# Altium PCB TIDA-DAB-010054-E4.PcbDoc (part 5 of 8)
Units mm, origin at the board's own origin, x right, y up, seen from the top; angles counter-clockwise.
Board outline 300 x 180 mm, 4 copper layers (Top Layer, Inner Layer1, Inner Layer2, Bottom Layer), stack 1.605 mm thick; 873 components, 388 nets, 2405 pads, 1542 vias.
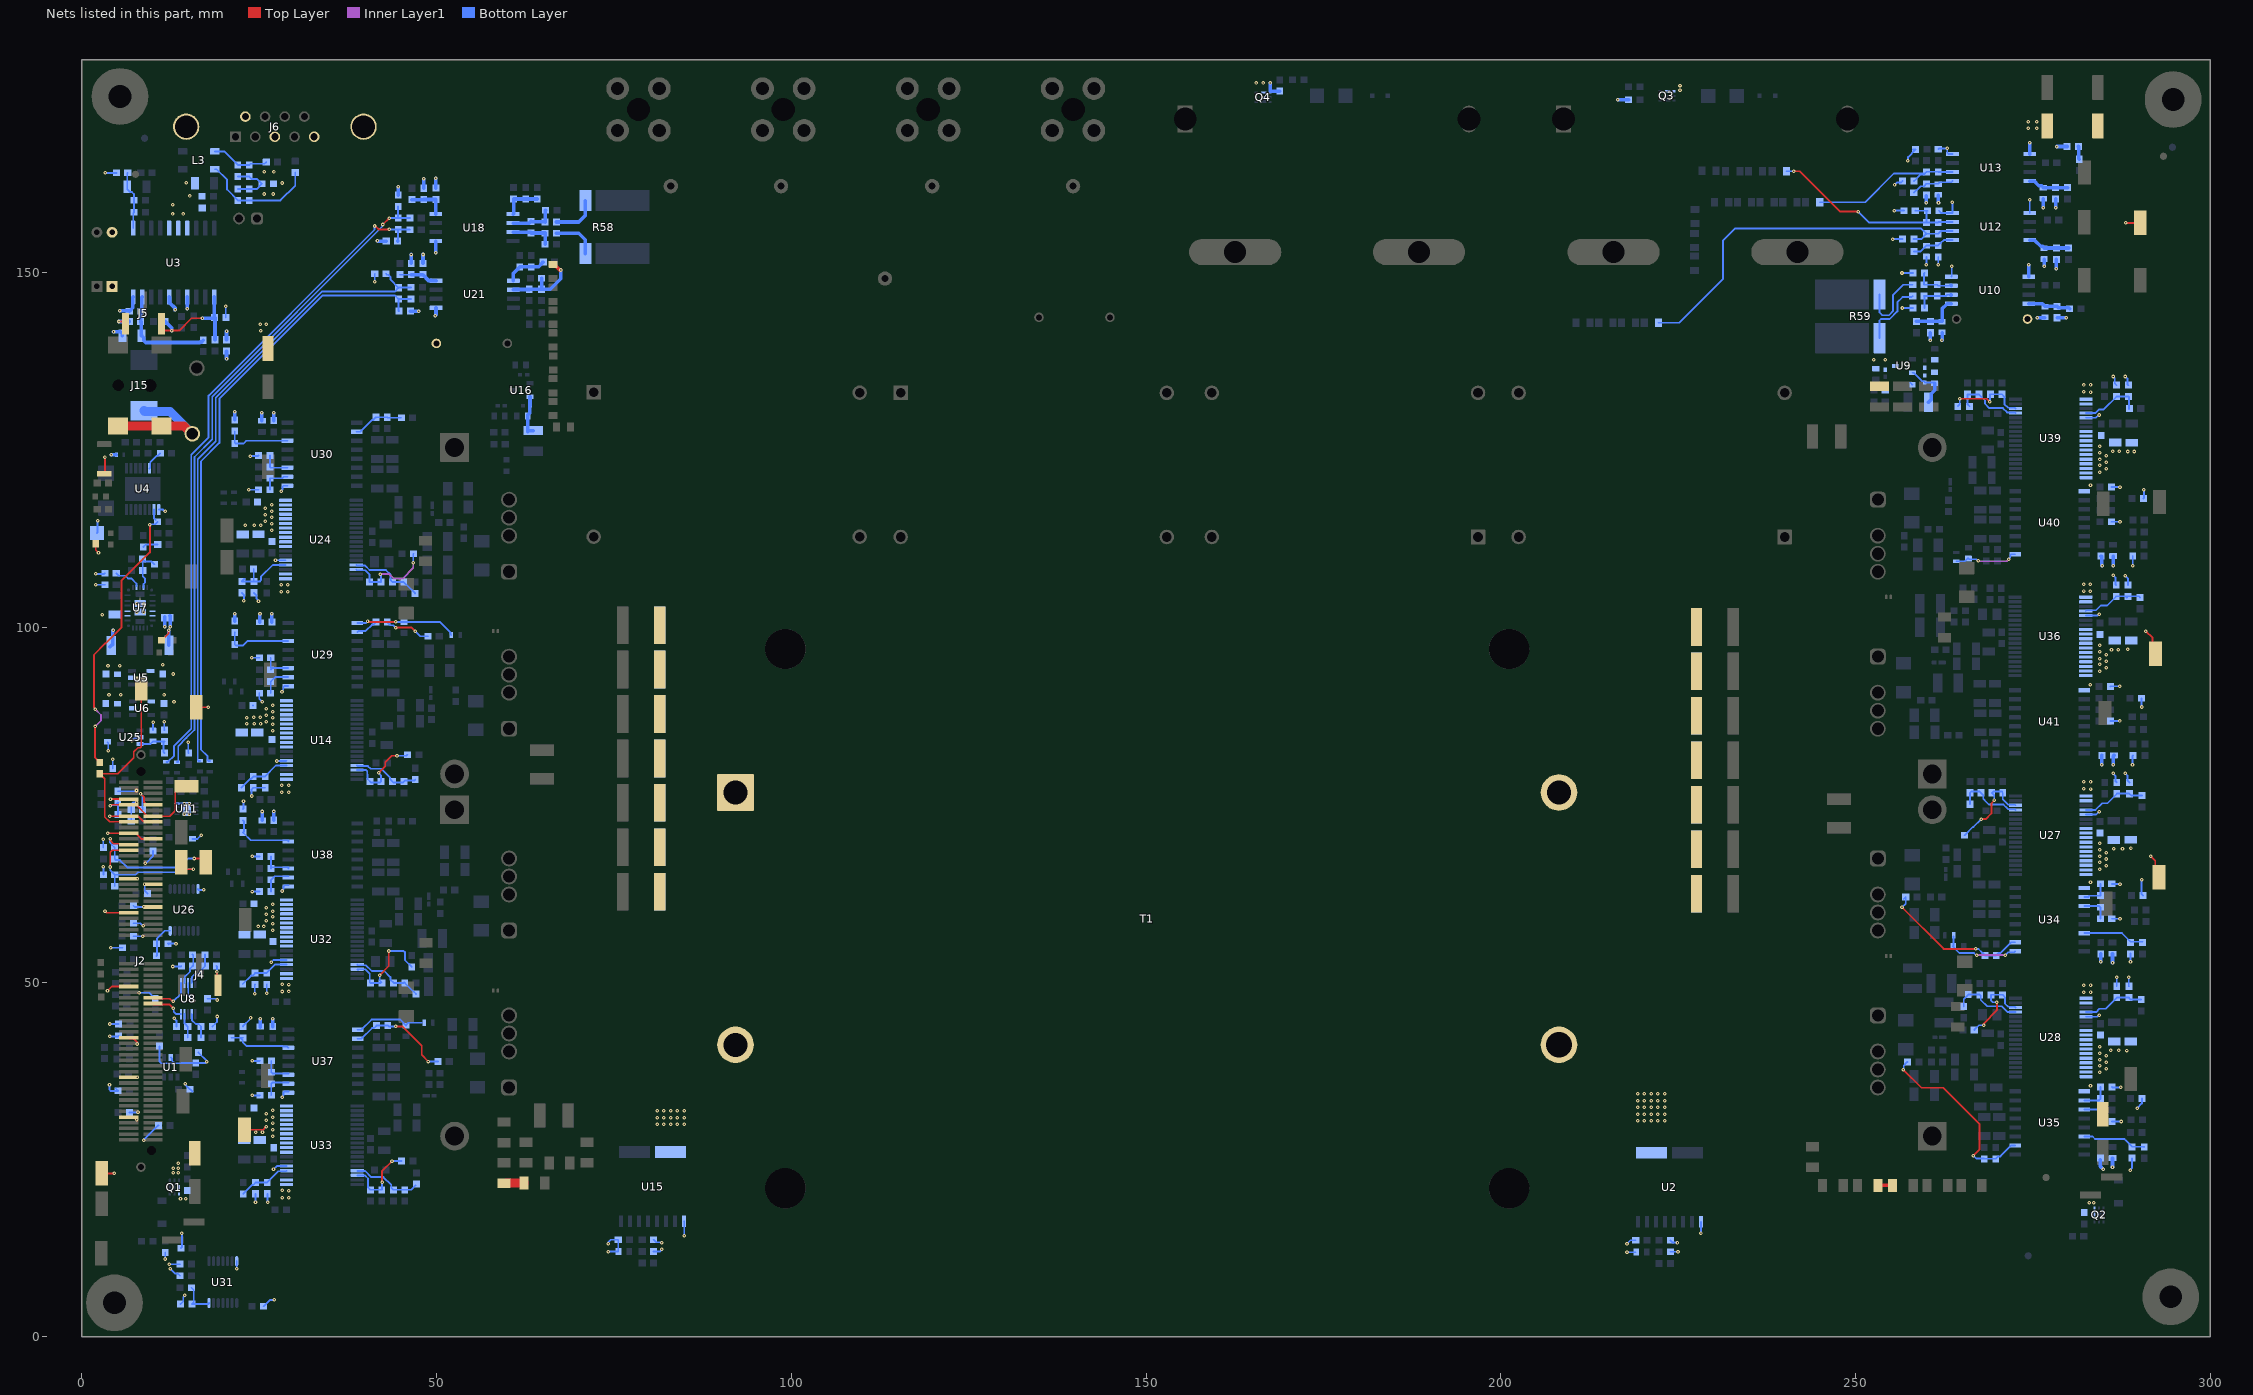
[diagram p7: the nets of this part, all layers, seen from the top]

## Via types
v1: diameter 0.5, hole 0.2, Top Layer to Bottom Layer, tented both sides, 1530 vias
v2: diameter 0.5, hole 0.2, Top Layer to Bottom Layer, 12 vias

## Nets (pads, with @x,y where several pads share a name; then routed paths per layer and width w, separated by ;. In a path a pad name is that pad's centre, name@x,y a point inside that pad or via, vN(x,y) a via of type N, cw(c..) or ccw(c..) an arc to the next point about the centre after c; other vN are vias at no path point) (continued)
GND: C1.2 C60.1 C61.2 C62.2 C63.2 C64.1 C65.2 C67.2 C68.1 C69.2 C70.1 C71.2 C72.2 C73.2 C74.2 C75.2 C77.2 C81.2 C82.2 C93.2 C96.2 C97.2 C98.2 C99.2 C100.2 C107.2 C108.2 C109.2 C110.2 C111.1 C112.2 C113.2 C114.2 C121.2 C122.2 C126.1 C128.2 C131.2 C132.2 C133.2 C134.2 C135.2 C136.2 C137.2 C138.2 C140.1 C141.2 C142.2 C145.2 C146.2 C147.2 C148.1 C149.2 C150.2 C151.2 C152.2 C153.2 C154.2 C155.2 C156.2 C157.2 C158.2 C159.2 C160.2 C175.2 C180.2 C183.2 C184.2 C185.2 C186.1 C187.1 C190.2 C191.1 C192.1 C194.2 C195.2 C197.2 C198.2 C199.2 C200.2 C201.2 C202.2 C203.2 C217.2 C222.2 C225.2 C226.2 C227.2 C228.1 C229.1 C231.2 C232.2 C233.1 C234.1 C236.2 C237.2 C238.2 C254.2 C259.2 C262.2 C264.2 C265.2 C266.1 C268.1 C270.2 C274.1 C275.2 C276.2 C277.2 C282.2 C293.2 C298.1 C299.2 C303.2 C304.2 C305.2 C306.1 C307.1 C309.2 C310.1 C311.1 C313.2 C314.2 C319.1 C320.1 C321.2 C322.2 C323.1 C324.1 C325.2 C326.2 C327.2 C328.2 C329.2 C330.2 C331.2 C332.2 C333.2 C334.2 D7.1 D9.2 J2.7 J2.10 J2.13 J2.16 J2.19 J2.22 J2.35 J2.38 J2.46 J2.47 J2.65 J2.83 J2.97 J2.111 J4.3 J9.1 J15.2 J15.3 L4.2 NT1.1 Q1.4 Q1.7 Q2.4 Q2.7 Q3.4 Q3.7 Q4.4 Q4.7 R2.1 R5.1 R28.2 R40.2 R43.1 R46.2 R51.1 R76.1 R81.1 R90.1 R93.1 R94.1 R99.1 R104.1 R130.1 R133.1 R134.1 R169.2 R174.1 R175.1 R176.1 R177.1 R178.1 R179.1 R180.1 R181.1 R182.1 R232.1 R233.1 R234.1 R235.1 R236.1 R237.1 R238.1 R239.1 R240.1 S1.2 TP11.1 TP25.1 TP26.1 TP27.1 TP28.1 TP29.1 TP31.1 U1.2 U2.3 U4.9 U5.2 U5.4 U6.2 U6.4 U7.5 U7.6 U7.16 U7.17 U7.28 U7.29 U8.3 U10.5 U11.4 U11.9 U12.5 U13.5 U14.1 U14.2 U14.5 U14.8 U14.9 U14.10 U14.11 U14.12 U14.13 U14.14 U14.15 U14.16 U14.17 U14.18 U15.3 U18.5 U21.5 U24.1 U24.2 U24.5 U24.8 U24.9 U24.10 U24.11 U24.12 U24.13 U24.14 U24.15 U24.16 U24.17 U24.18 U25.2 U26.7 U27.1 U27.2 U27.5 U27.8 U27.9 U27.10 U27.11 U27.12 U27.13 U27.14 U27.15 U27.16 U27.17 U27.18 U28.1 U28.2 U28.5 U28.8 U28.9 U28.10 U28.11 U28.12 U28.13 U28.14 U28.15 U28.16 U28.17 U28.18 U29.9 U30.9 U31.7 U32.1 U32.2 U32.5 U32.8 U32.9 U32.10 U32.11 U32.12 U32.13 U32.14 U32.15 U32.16 U32.17 U32.18 U33.1 U33.2 U33.5 U33.8 U33.9 U33.10 U33.11 U33.12 U33.13 U33.14 U33.15 U33.16 U33.17 U33.18 U34.9 U35.9 U36.1 U36.2 U36.5 U36.8 U36.9 U36.10 U36.11 U36.12 U36.13 U36.14 U36.15 U36.16 U36.17 U36.18 U37.9 U38.9 U39.1 U39.2 U39.5 U39.8 U39.9 U39.10 U39.11 U39.12 U39.13 U39.14 U39.15 U39.16 U39.17 U39.18 U40.9 U41.9 | length 311.9
  Top Layer w0.254: R76.1@2,111.77 2.014,111.756 2.014,110.889 2.389,110.514 v1(2.389,110.512) ; TP31.1@2.858,23.044 v1(4.623,23.044) ; S1.2@3.199,121.615 3.302,121.718 v1(3.302,123.985) ; v1(3.308,59.998) 3.528,59.779 J2.47@6.669,59.779 ; v1(3.656,48.786) 4.249,49.379 J2.65@6.669,49.379 ; v1(3.714,70.982) 3.716,70.981 7.632,70.981 8.434,70.179 J2.22@10.069,70.179 ; v1(3.978,73.379) J2.13@6.669,73.379 7.969,73.379 8.769,72.579 J2.16@10.069,72.579 ; v1(4.078,75.779) J2.7@6.669,75.779 ; J2.111@6.669,30.979 6.792,30.856 7.448,30.856 7.712,30.593 v1(7.808,30.593) ; J2.97@6.669,36.579 v1(7.847,36.579) ; J2.83@6.669,42.179 6.792,42.056 7.308,42.056 7.776,41.588 7.776,41.322 v1(7.823,41.275) ; J2.35@6.669,64.579 v1(7.871,64.579) ; v1(8.312,76.563) 8.786,76.09 8.786,75.415 9.222,74.979 J2.10@10.069,74.979 ; v1(8.786,60.595) 8.802,60.579 J2.46@10.069,60.579 ; v1(8.877,63.779) J2.38@10.069,63.779 ; R81.1@11.258,98.161 11.283,98.161 12.268,99.145 12.268,99.519 v1(12.315,99.566) ; TP29.1@16.155,88.714 v1(17.877,88.714) ; v1(19.084,51.441) 19.084,49.671 J4.3@19.202,49.552 ; TP25.1@22.96,29.2 25.584,29.2 25.984,29.6 v1(26.051,29.6) ; v1(288.058,156.98) TP28.1@290.09,156.98 ; v1(290.882,99.462) 291.846,98.498 291.846,96.668 TP26.1@292.252,96.262 ; v1(291.577,67.735) 292.227,67.085 292.227,65.29 TP27.1@292.751,64.766
  Top Layer w1.27: J15.2@5.155,128.386 J15.3@11.255,128.386 14.407,128.386 15.539,127.254 TP11.1@15.621,127.254 ; C314.2@26.11,139.451 C314.2@26.275,139.286
  Bottom Layer w0.254: v1(1.985,107.511) 3.198,107.511 C70.1@3.292,107.605 ; v1(2.014,106) C77.2@3.292,106 ; D9.2@2.18,113.27 2.261,113.352 v1(2.261,115.02) ; C114.2@3.067,68.973 3.067,70.108 v1(3.075,70.116) ; C153.2@3.08,65.131 v1(3.08,66.232) ; C146.2@3.662,83.793 3.767,83.688 v1(3.767,82.591) ; v1(3.937,35.531) 3.937,34.823 4.089,34.671 C107.2@5.156,34.671 C107.2@4.823,35.004 ; v1(3.946,42.344) 5.146,42.344 C323.1@5.22,42.418 ; v1(3.962,44.094) C324.1@5.22,44.094 ; v1(4.099,54.848) R178.1@5.763,54.848 ; C152.2@4.394,80.079 4.394,81.403 v1(4.405,81.414) ; R28.2@5.106,76.885 7.569,76.885 7.678,76.994 v1(7.745,76.994) ; C108.2@6.766,31.632 v1(7.956,31.632) ; v1(7.1,84.043) 7.456,84.399 8.127,84.399 U25.2@8.225,84.498 ; R180.1@7.304,58.277 8.295,58.277 8.635,57.937 v1(8.702,57.937) ; R179.1@7.316,56.453 v1(8.608,56.453) ; R181.1@7.326,60.762 7.492,60.595 v1(8.786,60.595) ; v1(8.101,48.494) 9.545,48.494 10.01,48.029 10.035,48.029 10.383,47.681 C322.2@10.383,47.656 ; v1(8.312,76.563) 8.608,76.268 C128.2@8.608,74.317 ; v1(8.788,27.736) 8.788,27.761 10.824,29.796 C93.2@10.849,29.796 ; v1(8.877,63.779) 8.913,63.743 8.913,62.843 9.261,62.495 R182.1@9.286,62.495 ; v1(8.968,66.732) 9.015,66.779 9.117,66.779 10.064,67.726 C140.1@10.064,68.479 ; C151.2@10.051,85.493 10.09,85.532 v1(10.09,86.621) ; U4.9@10.882,116.587 11.472,116.587 11.684,116.375 v1(11.78,116.375) ; C320.1@11,40.969 11,40.001 10.998,39.999 10.998,38.785 11.221,38.562 13.121,38.562 ; v1(11.667,86.679) 11.667,85.527 R169.2@11.682,85.513 ; v1(11.787,10.973) R240.1@11.787,11.895 ; C154.2@12.289,55.315 C154.2@12.191,55.414 v1(13.311,55.414) ; v1(12.344,10.24) R239.1@13.875,10.24 ; v1(12.5,9.596) 13.18,8.915 13.564,8.915 R236.1@13.875,8.604 ; U1.2@12.578,39.392 12.751,39.219 12.751,38.932 13.121,38.562 ; v1(12.824,52.195) 14.003,52.195 C137.2@14.06,52.252 ; v1(13.064,44.876) 13.372,44.568 C136.2@13.372,43.747 ; U11.4@13.455,75.159 v1(14.455,75.159) ; C197.2@13.949,4.634 13.974,4.634 14.322,4.982 14.322,5.571 14.526,5.775 v1(14.526,5.841) ; R238.1@14.003,12.482 14.148,12.627 v1(14.148,14.605) ; v1@14.574,35.7 v1(14.593,35.7) 14.64,35.652 14.64,35.511 15.263,34.889 C321.2@15.288,34.889 15.313,34.889 C321.2@15.661,34.541 ; U8.3@15.025,49.881 15.025,48.104 v1(15.79,47.339) ; v1(15.046,83.766) 15.046,82.311 C135.2@15.093,82.264 ; C126.1@15.621,70.17 16.338,70.17 v1(16.869,70.701) ; U26.7@16.393,63.121 16.393,63.075 16.484,62.984 v1(17.243,62.984) ; C319.1@16.457,40.07 16.482,40.07 17.626,38.926 17.626,38.799 v1(17.673,38.751) ; 17.46,38.605 C1.2@16.098,38.605 14.144,38.605 14.1,38.562 13.121,38.562 ; C313.2@17.752,47.656 18.902,47.656 19.085,47.473 v1(19.152,47.473) ; C121.2@18.431,43.747 18.456,43.747 18.804,44.095 18.804,44.12 19.109,44.425 v1(19.109,45.146) ; C122.2@19.027,52.252 19.084,52.195 v1(19.084,51.441) ; v1@21.864,9.596 U31.7@21.864,10.677 ; R93.1@22.6,104.862 22.885,104.576 v1(22.885,103.734) ; C265.2@22.737,43.747 22.737,43.772 23.814,44.849 v1(23.814,44.986) ; C270.2@22.751,74.388 22.82,74.457 v1(22.82,75.492) ; v1(23.566,119.377) C180.2@24.944,119.377 ; v1(23.803,124.117) 24.855,124.117 C184.2@24.944,124.206 ; v1(23.959,76.222) 23.959,77.134 R90.1@24.206,77.381 C159.2@25.883,77.381 ; v1(23.998,95.715) 25.054,95.715 C183.2@25.059,95.71 ; v1(24.038,34.034) 25.12,34.034 C254.2@25.145,34.059 ; v1(24.038,38.889) 25.12,38.889 C262.2@25.145,38.914 ; v1(24.038,62.758) 25.095,62.758 C259.2@25.097,62.756 ; v1(24.073,67.702) 25.095,67.702 C264.2@25.097,67.704 ; R177.1@24.16,88.981 R177.1@24.185,88.981 ; C160.2@24.288,104.862 24.636,104.514 24.636,104.057 24.937,103.757 v1(24.937,103.69) ; v1(24.409,48.336) 24.409,49.632 R104.1@24.46,49.682 ; v1(24.511,18.951) R130.1@24.511,20.168 ; C175.2@25.056,90.716 25.056,89.909 v1(25.48,89.484) ; R237.1@25.648,4.319 25.673,4.319 26.566,5.213 v1(27.134,5.213) ; C232.2@26.086,49.682 26.097,49.671 v1(26.097,48.452) ; C236.2@26.162,20.168 26.218,20.111 v1(26.218,18.951) ; v1(26.751,52.816) 27.05,53.115 U32.5@28.905,53.115 ; v1(27.051,23.627) 27.499,24.075 U33.5@28.905,24.075 ; v1(27.331,109.435) U24.5@28.765,109.435 ; v1(27.534,81.153) 27.548,81.167 28.852,81.167 U14.5@28.866,81.181 ; v1@28.14,90.84 28.14,90.907 28.418,91.184 28.418,91.527 28.591,91.7 U29.9@29.116,91.7 ; v1(28.145,119.153) 28.145,119.249 28.317,119.421 28.317,119.768 28.49,119.941 U30.9@29.015,119.941 ; v1@28.179,33.734 28.179,33.801 28.457,34.078 28.457,34.422 28.63,34.595 U37.9@29.155,34.595 ; v1@28.179,62.774 28.179,62.841 28.457,63.118 28.457,63.462 28.63,63.635 U38.9@29.155,63.635 ; C195.2@41.312,149.81 41.319,149.803 v1(41.319,148.701) ; v1(74.22,12.024) 75.625,12.024 C147.2@75.625,13.702 74.573,13.702 74.22,13.35 74.22,13.139 v1(74.231,13.128) ; R46.2@80.607,12.04 80.62,12.052 81.547,12.052 81.547,12.08 81.737,12.271 v1(81.737,12.337) ; C334.2@80.62,13.691 80.968,13.343 81.587,13.343 81.671,13.259 v1(81.737,13.259) ; U15.3@84.912,16.309 84.929,16.292 84.929,14.256 v1(84.945,14.24) ; v1(217.782,11.94) C111.1@219.02,11.94 ; v1(217.782,13.127) 218.275,13.62 C110.2@219.02,13.62 ; C333.2@223.888,13.614 224.218,13.284 v1(224.892,13.284) ; R40.2@223.914,11.989 v1(224.968,11.989) ; v1(228.205,14.6) U2.3@228.205,16.205 ; U12.5@274.543,158.367 v1(274.543,160.223) ; U36.5@282.426,101.638 284.041,101.638 284.256,101.853 v1(284.323,101.853) ; U28.5@282.475,45.12 284.038,45.12 284.246,45.329 v1(284.343,45.329) ; U27.5@282.475,73.605 283.875,73.605 284.246,73.976 v1(284.343,73.976) ; U39.5@282.475,129.53 283.864,129.53 284.246,129.913 v1(284.343,129.913) ; C304.2@285.889,86.793 v1(287.232,86.793) ; C299.2@285.889,91.65 285.923,91.685 v1(287.232,91.685) ; C303.2@286.036,114.861 286.044,114.854 v1(287.252,114.854) ; C293.2@286.036,119.763 286.054,119.745 v1(287.252,119.745) ; C225.2@286.085,58.917 v1(287.252,58.917) ; C217.2@286.085,63.85 286.126,63.808 v1@287.342,63.808 ; C226.2@286.125,30.354 v1(287.432,30.354) ; C222.2@286.125,35.211 286.176,35.161 v1(287.342,35.161) ; v1(286.275,107.344) 286.607,107.011 286.607,106.056 C282.2@286.706,105.957 ; v1(286.3,79.402) 286.3,79.342 286.639,79.003 286.639,78.283 C202.2@286.79,78.132 ; v1(286.3,135.338) 286.3,135.278 286.512,135.066 286.512,134.357 C277.2@286.759,134.109 ; v1(286.8,50.688) 286.8,49.42 C203.2@286.805,49.416 ; v1(287.985,107.278) 288.363,106.9 R133.1@288.363,105.957 ; v1(288.005,79.402) 288.293,79.114 288.293,78.422 R94.1@288.583,78.132 ; v1(288.005,135.338) 288.29,135.053 288.29,134.264 R134.1@288.444,134.109 ; v1(288.48,50.688) 288.48,49.445 R99.1@288.51,49.416 ; v1(288.7,23.487) 288.7,23.553 288.955,23.808 C231.2@288.955,25.183 ; v1(288.73,52.859) C227.2@288.73,54.074 ; v1(289.016,80.612) 289.016,81.854 C309.2@289.097,81.935 ; v1(289.036,108.672) C305.2@289.036,110.028 ; v1(289.685,32.246) 290.335,32.896 R234.1@290.335,33.58 ; v1(290.289,64.396) 290.289,62.392 R235.1@290.485,62.196 ; v1(290.289,88.76) R232.1@290.289,89.999 ; R233.1@290.561,118.129 290.625,118.193 v1(290.625,119.401)
  Bottom Layer w0.508: C71.2@4.013,97.232 4.422,97.641 4.422,99.546 v1(4.442,99.566) ; v1(4.202,124.308) C62.2@4.851,124.308 ; v1(11.716,100.084) C74.2@11.716,101.476 ; C72.2@12.315,97.491 v1(12.315,99.566) ; C74.2@12.467,101.631 12.501,101.597 v1(12.501,100.084) ; v1(20.432,137.859) L4.2@20.432,138.909 ; v1(21.6,101.895) 21.6,100.889 C185.2@21.605,100.884 ; C190.2@21.6,129.229 v1(21.6,130.344) ; C186.1@25.134,100.727 25.134,101.904 v1(25.146,101.915) ; C266.1@25.174,43.621 C266.1@25.174,43.747 ; v1(25.185,44.809) 25.19,44.804 C266.1@25.19,43.747 ; C191.1@25.411,129.122 v1(25.411,130.237) ; C274.1@25.453,72.8 v1(25.453,74.033) ; v1(26.821,101.904) 26.83,101.895 C187.1@26.83,100.745 ; v1(26.948,44.847) 26.948,43.762 C268.1@26.962,43.747 ; C192.1@27.079,129.122 27.089,129.132 27.089,130.228 v1(27.099,130.237) ; v1(27.087,74.04) 27.094,74.033 27.094,72.807 C298.1@27.101,72.8 ; v1(41.701,154.451) 41.729,154.451 41.765,154.415 C133.2@42.94,154.415 ; C134.2@44.613,160.9 44.616,160.903 44.616,162.078 v1(44.628,162.09) ; C194.2@46.329,144.556 46.342,144.543 47.497,144.543 v1(47.509,144.53) ; C142.2@46.479,151.285 v1(46.479,152.522) ; C141.2@48.106,151.285 48.113,151.293 48.113,152.522 v1(48.121,152.529) ; C131.2@48.229,161.867 48.232,161.871 48.232,163.187 v1(48.235,163.19) ; v1(49.845,143.885) 49.845,143.913 49.953,144.021 U21.5@49.953,145.012 ; v1(49.91,152.8) U18.5@49.91,154.415 ; v1(49.91,163.283) 49.921,163.272 49.921,161.892 C132.2@49.933,161.881 ; v1(167.507,176.698) 167.507,175.593 167.56,175.54 R43.1@168.86,175.54 ; v1(216.45,174.32) R51.1@218,174.32 ; U10.5@274.39,149.405 v1(274.39,151.062) ; U13.5@274.55,166.685 274.55,168.248 v1(274.562,168.26) ; v1(275.573,143.614) C81.2@276.676,143.614 ; v1(276.44,159.13) C99.2@276.44,160.357 ; v1(276.56,150.844) C97.2@276.56,151.842 ; v1(278.171,159.13) C100.2@278.171,160.357 ; v1(278.291,150.54) C98.2@278.291,151.842 ; v1(278.355,167.74) C109.2@279.796,167.74 ; C82.2@278.392,143.614 v1(279.694,143.614) ; C234.1@284.493,24.969 284.493,24.019 v1(284.877,23.635) ; v1(284.525,52.837) C229.1@284.525,53.974 ; C307.1@284.579,110.028 284.708,109.898 284.708,108.692 v1(284.728,108.672) ; v1@284.707,80.613 C311.1@284.707,81.935 ; v1(286.199,23.891) C233.1@286.199,25.183 ; v1(286.2,52.736) C228.1@286.2,53.974 ; C306.1@286.287,110.028 286.303,110.011 286.303,108.689 v1(286.32,108.672) ; v1@286.3,80.64 286.3,81.835 C310.1@286.4,81.935
  Bottom Layer w1.27: D7.1@8.776,130.517 8.908,130.385 12.49,130.385 TP11.1@15.621,127.254
  other v1: 21.864,9.581 282.89,18.922 283.536,18.922 13.945,19.45 14.697,19.45 28.28,19.631 29.21,19.636 29.21,20.614 28.28,20.641 12.903,23.114 13.64,23.114 12.903,23.774 13.64,23.774 13.64,24.46 26.961,28.283 24.536,28.854 25.502,28.854 26.961,29.2 26.961,30.137 26.051,30.5 26.961,30.958 26.051,31.433 26.961,31.916 28.285,33.793 283.095,35.402 284.419,37.279 285.329,37.762 284.419,38.237 285.329,38.695 284.419,39.058 285.329,39.595 284.419,39.995 288.18,40.352 285.945,40.378 287.088,40.378 284.419,40.912 283.1,48.554 282.17,48.581 28.28,48.671 29.21,48.676 282.17,49.559 283.1,49.564 29.21,49.654 28.28,49.681 26.961,57.323 24.892,57.836 25.654,57.836 26.961,58.24 26.051,58.64 26.961,59.177 26.051,59.54 26.961,59.998 26.051,60.473 26.961,60.956 28.285,62.833 287.252,63.808 283.095,64.049 284.419,65.927 285.329,66.41 284.419,66.884 285.329,67.342 284.419,67.706 285.329,68.242 284.419,68.642 286.36,68.809 287.604,68.809 288.798,68.834 284.419,69.559 14.455,73.659 15.155,73.659 14.805,74.409 15.155,75.159 28.241,76.736 29.17,76.742 283.1,77.201 282.17,77.228 29.17,77.72 28.241,77.747 282.17,78.206 283.1,78.212 284.708,80.612 286.3,80.612 26.922,85.389 26.922,86.306 23.266,86.374 24.322,86.385 25.222,86.385 26.011,86.706 26.922,87.242 23.266,87.274 24.282,87.3 25.182,87.3 26.011,87.606 26.922,88.064 26.011,88.539 26.922,89.022 13.029,89.484 3.867,90.463 5.52,90.463 11.625,90.463 28.246,90.899 283.075,91.926 12.92,93.41 284.399,93.803 285.309,94.286 3.73,94.576 5.367,94.59 11.458,94.694 284.399,94.761 285.309,95.218 284.399,95.582 285.309,96.118 284.399,96.518 286.055,96.825 286.995,96.85 288.315,96.876 284.399,97.435 2.894,101.773 7.751,102.135 8.751,102.135 7.751,103.335 8.751,103.335 28.14,104.991 29.07,104.996 283.08,105.078 282.15,105.105 29.07,105.974 28.14,106.001 282.15,106.082 283.08,106.088 26.821,113.643 25.273,114.376 23.063,114.402 24.333,114.402 26.821,114.56 25.911,114.96 26.821,115.497 25.911,115.86 26.821,116.318 25.911,116.793 26.821,117.276 283.095,119.986 284.419,121.863 285.329,122.346 284.419,122.821 285.329,123.278 284.419,123.642 285.329,124.178 284.419,124.578 288.366,124.765 289.255,124.765 286.207,124.79 287.147,124.79 284.419,125.496 283.1,133.138 282.17,133.165 282.17,134.143 283.1,134.148 25.247,141.791 25.182,142.705 26.036,142.708 274.333,170.33 275.507,170.33 274.333,171.23 275.507,171.23 225.251,175.653 225.251,176.337 165.557,176.698 166.532,176.698
GND_CAN: C2.2 C3.2 C4.2 C5.2 J5.1 L4.1 U3.4 U3.6 U3.10 | length 14.2
  Top Layer w0.254: v1(5.274,143.086) 5.882,143.086 J5.1@6.185,142.783
  Bottom Layer w0.254: C5.2@20.333,143.656 v1(20.333,145.238)
  Bottom Layer w0.508: v1(4.508,141.65) 5.463,141.65 5.759,141.354 C2.2@5.759,141.102 ; v1(5.274,143.086) C3.2@6.722,143.086 ; v1@5.403,144.611 6.647,144.611 C4.2@6.722,144.536 ; C4.2@6.822,144.611 7.229,145.018 7.229,146.494 U3.10@7.275,146.54 ; U3.6@12.355,146.54 12.401,146.494 12.401,145.744 13.164,144.981 13.164,144.733 v1(13.183,144.713) ; v1(14.895,144.869) U3.4@14.895,146.54 ; L4.1@20.432,140.509 v1(20.432,141.739)
  other v1: 5.375,144.611
GND_ISO_CAN: C6.2 C7.2 C8.2 C10.1 J6.3 J6.5 J6.6 J6.10 J6.11 J9.2 L6.1 U3.15 U3.16 U3.17 | length 1.6
  Bottom Layer w0.254: v1(3.326,164.029) L6.1@4.917,164.029
  other v1: 12.823,158.238 14.314,158.238 12.878,159.551 15.22,160.775 25.767,161.053 27.042,161.053 28.26,162.602 14.745,162.647 25.767,164.188 27.117,164.188
GND_SEN_SEC: C79.2 C80.2 C83.1 C84.2 C85.1 C86.1 C87.2 C90.1 C91.2 C92.2 C101.2 C102.2 C103.2 C104.2 C239.2 C263.2 C267.2 C271.2 D11.2 R22.2 R23.2 R87.2 R342.2 U9.3 U10.4 U12.4 U13.4 | length 25
  Bottom Layer w0.254: R87.2@254.166,133.396 254.191,133.396 254.539,133.744 R87.2@254.539,133.769 ; v1(255.252,154.702) C239.2@256.598,154.702 ; v1(255.434,158.707) C267.2@256.796,158.707 ; v1(255.48,162.344) 255.799,162.663 256.386,162.663 C263.2@256.598,162.875 ; v1(256.533,149.92) C92.2@258.102,149.92 ; v1(256.6,144.987) C83.1@258.113,144.987 ; v1(257.352,165.724) 257.399,165.771 257.399,166.253 258.427,167.281 C271.2@258.427,167.306 ; D11.2@257.727,134.457 D11.2@258,134.184 ; v1(259.976,151.088) C102.2@259.976,152.194 ; v1(261.642,151.062) C101.2@261.642,152.194 ; R22.2@261.642,167.356 261.769,167.483 v1(262.904,167.483) 262.916,167.471 262.916,166.858 263.089,166.685 U13.4@263.65,166.685 ; R23.2@261.749,158.703 262.085,158.367 U12.4@263.643,158.367 v1(263.643,159.875) ; U10.4@263.49,149.405 263.548,149.463 v1(263.548,150.844) ; C271.2@258.427,167.306 258.07,167.306 C271.2@258.427,167.306
  Bottom Layer w0.508: C103.2@259.976,160.808 v1(259.976,159.814) v1(259.976,159.814) ; v1(260.522,140.43) 260.537,140.445 C79.2@260.537,141.498 ; C104.2@261.642,160.883 261.642,159.869 v1(261.678,159.833) ; v1(262.164,140.42) 262.179,140.435 C80.2@262.179,141.498
  other v1: 254.175,137.678 252.566,137.716
I_DC_PRI: C128.1 J2.14 R139.2 TP8.1 | length 14.7
  Top Layer w0.254: v1(7.756,75.363) 7.756,74.921 9.298,73.379 10.831,73.379 12.419,73.379 13.192,74.152 13.192,76.853 13.954,77.615 TP8.1@14.78,77.615
  Bottom Layer w0.254: R139.2@7.014,72.673 7.008,72.678 7.008,75.068 7.255,75.316 7.709,75.316 v1(7.756,75.363)
I_OUT_N: R59.2 R91.1 | length 10.5
  Bottom Layer w0.254: R59.2@253.366,146.893 253.366,144.373 253.763,143.976 254.703,143.976 255.252,144.525 255.252,146.808 256.716,148.272 R91.1@258.045,148.272
I_OUT_P: R59.1 R89.1 | length 9.3
  Bottom Layer w0.254: R59.1@253.366,140.743 253.366,143.222 253.58,143.437 254.815,143.437 255.89,144.512 255.89,145.803 256.624,146.537 257.909,146.537 R89.1@258.045,146.672
I_PRI_P: T1.2 U15.2
  other v1: 81.11,29.937 82.063,29.937 83.015,29.937 83.968,29.937 84.92,29.937 81.11,30.877 82.063,30.877 83.015,30.877 83.968,30.877 84.92,30.877 81.11,31.842 82.063,31.842 83.015,31.842 83.968,31.842 84.92,31.842
I_SEC_P: T1.3 U2.1
  other v1: 219.285,30.451 220.237,30.451 221.19,30.451 222.142,30.451 223.095,30.451 219.285,31.391 220.237,31.391 221.19,31.391 222.142,31.391 223.095,31.391 219.285,32.356 220.237,32.356 221.19,32.356 222.142,32.356 223.095,32.356 219.285,33.295 220.237,33.295 221.19,33.295 222.142,33.295 223.095,33.295 219.285,34.26 220.237,34.26 221.19,34.26 222.142,34.26 223.095,34.26
I_TANK_PRI: C153.1 J2.25 R168.2 TP19.1 | length 21.5
  Top Layer w0.254: v1(4.043,66.219) 4.043,68.305 4.317,68.579 J2.25@6.669,68.579 ; TP19.1@14.057,66.89 14.057,66.654 14.819,65.892 v1(15.772,65.892)
  Bottom Layer w0.254: v1(4.043,66.219) 4.043,65.768 4.307,65.504 4.307,65.479 4.656,65.13 C153.1@4.68,65.13 ; R168.2@4.68,63.492 C153.1@4.68,65.13 ; v1(15.772,65.892) 14.157,65.892 13.754,65.489 7.96,65.489 7.601,65.13 C153.1@4.68,65.13
I_TANK_SEC: C114.1 J2.23 R126.2 TP17.1 | length 20.1
  Top Layer w0.254: v1(4.043,70.179) 4.09,70.132 4.09,69.917 4.505,69.502 6.546,69.502 J2.23@6.669,69.379 ; v1(15.866,67.415) 17.376,67.415 TP17.1@17.52,67.271
  Bottom Layer w0.254: v1(4.043,70.179) 4.017,70.154 4.017,69.623 4.294,69.346 4.294,69.321 4.642,68.973 C114.1@4.667,68.973 4.667,67.358 4.831,67.194 5.407,67.194 6.45,66.151 13.771,66.151 15.034,67.415 v1(15.866,67.415)
ID_A: J2.9 R15.1 R28.1 | length 5.6
  Top Layer w0.254: v1(4.041,74.832) 4.108,74.832 4.255,74.979 J2.9@6.669,74.979
  Bottom Layer w0.254: v1(4.041,74.832) 4.108,74.832 4.188,74.912 4.758,74.912 5.106,75.26 R28.1@5.106,75.285 5.15,75.241 R15.1@5.15,73.632
Iin+: R58.3 R136.1 | length 6.5
  Bottom Layer w0.508: R136.1@66.936,157.107 70.069,157.107 70.992,158.029 R58.3@70.992,160.115
Iin-: R58.4 R140.1 | length 6.4
  Bottom Layer w0.508: R140.1@66.936,155.52 70.056,155.52 70.991,154.585 R58.4@70.992,152.648
IMON_EFUSE: R72.1 R74.2 U4.10 | length 40.7
  Top Layer w0.254: v1(1.926,86.019) 1.908,86.001 1.908,81.639 2.564,80.984 R72.1@2.564,80.959 ; v1(1.926,88.441) 1.926,88.508 1.752,88.682 1.752,96.11 3.36,97.718 3.414,97.718 5.622,99.925 5.622,106.529 9.64,110.547 v1(9.64,114.452)
  Inner Layer1 w0.254: v1(1.926,86.019) 2.738,86.83 2.738,87.629 v1(1.926,88.441)
  Bottom Layer w0.254: v1(9.64,114.452) 9.712,114.524 10.383,114.524 R74.2@10.729,114.869 ; U4.10@10.232,116.587 10.232,115.346 10.465,115.113 R74.2@10.465,115.087
IMON_MCU: J2.15 R72.2 TP10.1 | length 26.2
  Top Layer w0.254: R72.2@2.564,79.359 5.106,79.359 7.364,81.617 7.364,82.445 7.953,83.033 8.259,83.033 8.408,83.182 TP10.1@8.408,91.367 ; R72.2@2.564,79.384 2.564,79.334 2.912,78.986 2.937,78.986 3.274,78.649 3.274,73.263 3.957,72.579 J2.15@6.669,72.579
MODE_EFUSE: R77.2 U4.6 | length 2.8
  Bottom Layer w0.254: U4.6@9.582,122.387 9.677,122.482 9.677,123.245 10.591,124.159 10.757,124.159 R77.2@11.105,124.507
MPP: R226.1 R281.2 | length 2.9
  Top Layer w1.27: R226.1@59.525,21.635 59.8,21.635 59.862,21.697 R281.2@62.365,21.697
MPS: R228.1 R285.2 | length 2
  Top Layer w0.508: R228.1@253.163,21.345 R285.2@255.205,21.345
MUX_A0: J2.70 U8.1 | length 6.1
  Top Layer w0.254: J2.70@10.069,47.779 10.192,47.656 12.451,47.656 12.834,47.273 v1(12.914,47.273)
  Bottom Layer w0.254: v1@12.92,47.278 14.025,48.384 U8.1@14.025,49.881
MUX_A1: J2.72 U8.10 | length 4.8
  Top Layer w0.254: J2.72@10.069,46.979 10.192,46.856 12.375,46.856 v1(12.914,46.317)
  Bottom Layer w0.254: v1(12.914,46.317) 12.982,46.249 12.982,45.827 13.329,45.481 U8.10@14.025,45.481
NetC2_1: C2.1 C3.1 C4.1 L1.1 U3.9 | length 15.1
  Bottom Layer w0.508: U3.9@8.545,146.54 8.499,146.494 8.499,144.713 C4.1@8.322,144.536 C3.1@8.322,143.086 8.39,143.018 8.39,141.171 8.755,140.806 8.755,140.422 9.052,140.124 16.628,140.124 16.707,140.203 16.926,140.203 17.147,140.424 L1.1@17.147,140.449
NetC5_1: C5.1 J5.3 L2.1 R52.1 U3.1 | length 16.7
  Top Layer w0.254: J5.3@11.265,142.783 11.265,142.181 11.638,141.808 v1(12.7,141.808) 13.755,141.808 15.494,143.548 v1(17.04,143.548)
  Bottom Layer w0.508: R52.1@11.752,143.086 11.973,142.865 11.998,142.865 12.7,142.163 v1(12.7,141.808) ; v1@17.067,143.548 18.625,143.548 C5.1@18.733,143.656 ; U3.1@18.705,146.54 18.705,143.685 C5.1@18.733,143.656 ; L2.1@18.808,140.509 18.808,143.581 C5.1@18.733,143.656
NetC9_1: C9.1 C10.2 C11.2 R54.1 R55.2 | length 7.6
  Bottom Layer w0.254: R55.2@22.008,163.527 C11.2@23.637,163.527 23.712,163.452 23.712,163.427 23.985,163.154 24.763,163.154 C10.2@25.417,162.5 ; R54.1@22.017,161.75 C9.1@23.637,161.75 24.667,161.75 C10.2@25.417,162.5 ; C10.2@25.442,162.5 C10.2@25.417,162.5
NetC9_2: C9.2 L3.4 R53.1 R54.2 | length 16.7
  Bottom Layer w0.254: L3.4@18.795,164.55 19.02,164.55 20.506,163.064 20.506,161.687 22.017,160.175 R54.2@22.017,160.15 C9.2@23.637,160.15 28.023,160.15 30.112,162.239 R53.1@30.112,164.077
NetC11_1: C11.1 L3.3 R55.1 R56.1 | length 8.2
  Bottom Layer w0.254: L3.3@18.795,167.05 20.111,167.05 22.008,165.152 R55.1@22.008,165.127 C11.1@23.637,165.127 23.813,165.303 25.785,165.303 R56.1@26.03,165.547
NetC12_2: C12.2 C13.2 C14.2 L6.2 U3.11 | length 8.4
  Bottom Layer w0.254: L6.2@6.517,164.029 6.442,163.954 6.442,161.743 6.865,161.32 7.109,161.32 7.41,161.018 C13.2@7.41,160.162 7.4,160.152 C12.2@7.4,158.473 7.275,158.348 U3.11@7.275,156.24
NetC31_1: C31.1 C33.1 C35.1 C37.1 C39.1 C41.1 C43.1 C45.1 C47.1 C49.1 C51.1 C53.1 C55.1 C57.1 T1.1
NetC32_2: C32.2 C34.2 C36.2 C38.2 C40.2 C42.2 C44.2 C46.2 C48.2 C50.2 C52.2 C54.2 C56.2 C58.2 T1.4
NetC66_1: C66.1 R78.1 | length 2.2
  Bottom Layer w0.254: R78.1@8.713,111.322 9.046,111.656 10.727,111.656 C66.1@10.735,111.647
NetC70_2: C70.2 U7.23 | length 3.8
  Bottom Layer w0.254: C70.2@4.892,107.605 5.24,107.257 6.164,107.257 6.545,106.876 7.02,106.876 7.749,106.147 U7.23@7.749,105.808
NetC76_2: C76.2 R80.1 R83.1 U7.25 | length 6.2
  Bottom Layer w0.254: U7.25@8.751,105.585 8.753,105.587 8.753,106.101 8.958,106.307 8.958,106.833 8.622,107.169 R80.1@8.622,107.986 8.622,109.595 C76.2@8.615,109.602 8.64,109.602 8.988,109.254 9.872,109.254 10.249,108.877 R83.1@10.274,108.877
NetC78_2: C78.2 R16.1 U29.1 | length 14.3
  Top Layer w0.254: v1(40.301,100.835) 40.367,100.835 40.453,100.75 v1@44.238,100.75
  Bottom Layer w0.254: U29.1@38.866,100.59 40.038,100.59 40.283,100.835 v1(40.301,100.835) ; v1@44.238,100.75 45.461,100.75 50.482,100.75 52.001,99.231 52.001,99.012 R16.1@52.111,98.901
  other v1: 44.279,100.75
NetC79_1: C79.1 C80.1 L7.1 U10.1 | length 7
  Bottom Layer w0.508: L7.1@258.565,143.098 C79.1@260.537,143.098 262.179,143.098 262.179,144.884 262.89,145.595 U10.1@263.49,145.595
NetC81_1: C81.1 C82.1 L8.1 U10.8 | length 6.1
  Bottom Layer w0.508: U10.8@274.39,145.595 276.321,145.595 276.676,145.239 276.676,145.214 C82.1@278.392,145.214 278.572,145.034 280.011,145.034 L8.1@280.162,144.884
NetC83_2: C83.2 C89.1 R89.2 U10.2 | length 5.6
  Bottom Layer w0.254: R89.2@259.645,146.672 C89.1@261.504,146.672 262.697,146.672 262.89,146.865 U10.2@263.49,146.865 ; C83.2@259.713,144.987 R89.2@259.713,146.604
  Bottom Layer w0.508: U10.2@263.444,146.819 U10.2@263.49,146.865
NetC84_1: C84.1 C85.2 R88.2 U9.2 | length 6.8
  Bottom Layer w0.254: U9.2@257.996,135.866 258.196,135.866 259.402,134.66 259.647,134.66 259.77,134.537 C85.2@259.77,134.487 261.01,134.487 C84.1@261.139,134.358
  Bottom Layer w0.508: R88.2@260.261,131.7 260.657,132.096 260.657,132.895 261.139,133.377 C84.1@261.139,134.358
NetC88_2: C88.2 R17.1 U34.1 | length 11
  Inner Layer1 w0.254: v1(267.039,53.8) v1(271.092,53.8)
  Bottom Layer w0.254: R17.1@263.803,56.452 263.803,55.139 263.683,55.018 263.708,55.018 264.624,54.102 266.671,54.102 266.973,53.8 v1(267.039,53.8) ; v1(271.092,53.8) 271.498,54.206 272.326,54.206 U34.1@272.475,54.355
NetC89_2: C89.2 C92.1 R91.2 U10.3 | length 5.6
  Bottom Layer w0.254: C92.1@259.702,149.92 259.645,149.864 R91.2@259.645,148.272 C89.2@261.504,148.272 261.642,148.135 U10.3@263.49,148.135
  Bottom Layer w0.508: U10.3@263.444,148.181 U10.3@263.49,148.135
NetC94_2: C94.2 R18.1 U37.1 | length 10.2
  Bottom Layer w0.254: U37.1@38.905,43.285 39.43,43.285 40.872,44.727 44.896,44.727 C94.2@45.701,43.922 ; C94.2@45.701,43.897 C94.2@45.701,43.922 ; 48.017,44.27 46.049,44.27 C94.2@45.701,43.922
NetC95_2: C95.2 R29.1 U40.1 | length 9.1
  Inner Layer1 w0.254: v1(267.296,109.354) 267.339,109.311 271.279,109.311 271.523,109.555 v1(271.551,109.555)
  Bottom Layer w0.254: R29.1@264.167,109.29 265.388,109.29 265.782,109.684 C95.2@265.887,109.684 ; C95.2@265.952,109.574 267.009,109.574 267.23,109.354 v1(267.296,109.354) ; v1(271.551,109.555) 271.551,109.651 271.777,109.877 271.777,110.118 271.95,110.291 U40.1@272.475,110.291
NetC97_1: C97.1 C98.1 L9.1 U12.8 | length 5.9
  Bottom Layer w0.508: U12.8@274.543,154.557 274.589,154.511 275.257,154.511 276.08,153.688 276.339,153.688 276.56,153.467 276.56,153.442 C98.1@278.291,153.442 L9.1@279.991,153.442
NetC99_1: C99.1 C100.1 L10.1 U13.8 | length 5.4
  Bottom Layer w0.508: U13.8@274.55,162.875 275.15,162.875 275.822,162.203 C99.1@276.219,162.203 ; C99.1@276.44,161.957 C100.1@278.171,161.957 L10.1@279.871,161.957
NetC101_1: C101.1 C102.1 L11.1 U12.1 | length 6.1
  Bottom Layer w0.254: L11.1@258.198,152.96 259.166,152.96 259.976,153.769 259.976,153.794 C101.1@261.642,153.794 261.642,153.819 261.99,154.167 262.015,154.167 262.404,154.557 U12.1@263.643,154.557
NetC103_1: C103.1 C104.1 L12.1 U13.1 | length 6.1
  Bottom Layer w0.254: L12.1@258.182,161.232 258.53,161.58 258.624,161.58 259.195,162.151 259.644,162.151 C103.1@259.976,162.483 261.642,162.483 261.871,162.712 263.487,162.712 U13.1@263.65,162.875
NetC105_1: C105.1 C263.1 R111.1 R115.2 U13.2 | length 22.5
  Bottom Layer w0.254: R111.1@244.939,159.888 251.336,159.888 255.403,163.954 R115.2@259.774,163.954 ; C263.1@258.198,162.875 258.223,162.875 259.131,163.783 259.628,163.783 259.774,163.929 R115.2@259.774,163.954 ; C105.1@261.642,164.145 U13.2@263.65,164.145 ; C105.1@261.642,164.156 261.621,164.177 259.997,164.177 R115.2@259.976,164.156 R115.2@259.774,163.954
NetC106_1: C106.1 C239.1 R109.1 R114.2 U12.2 | length 52.7
  Bottom Layer w0.254: R109.1@222.209,142.912 225.149,142.912 231.319,149.082 231.319,154.513 232.986,156.18 259.248,156.18 259.603,155.825 259.628,155.825 259.976,155.477 R114.2@259.976,155.452 ; C239.1@258.173,154.702 259.251,154.702 259.976,155.427 R114.2@259.976,155.452 ; U12.2@263.643,155.827 262.138,155.827 262.136,155.825 261.99,155.825 261.642,155.477 C106.1@261.642,155.452 R114.2@259.976,155.452
NetC106_2: C106.2 C267.1 R23.1 R64.2 R114.1 U12.3 | length 29.9
  Top Layer w0.254: v1(241.26,164.256) 242.141,164.256 247.83,158.567 v1(250.36,158.567)
  Bottom Layer w0.254: R64.2@240.251,164.256 v1(241.26,164.256) ; v1(250.36,158.567) 251.875,157.052 R114.1@259.976,157.052 ; C267.1@258.396,158.707 258.401,158.703 R23.1@260.149,158.703 259.976,158.529 R114.1@259.976,157.052 ; U12.3@263.643,157.097 261.687,157.097 C106.2@261.642,157.052 R114.1@259.976,157.052
NetC109_1: C109.1 R118.1 | length 1.8
  Bottom Layer w0.508: C109.1@281.396,167.74 281.461,167.675 281.461,166.015 R118.1@281.525,165.95
NetC115_1: C115.1 C116.2 R129.2 U16.2 | length 5.9
  Bottom Layer w0.508: U16.2@63.197,132.476 63.201,132.471 63.201,131.24 C116.2@63.206,131.236 ; C116.2@63.206,131.236 63.164,131.236 63.16,131.232 63.16,130.994 63.143,130.977 63.143,130.171 62.922,129.95 62.897,129.95 62.893,129.946 62.893,127.586 63.024,127.717 R129.2@63.647,127.717
NetC121_1: C121.1 R30.1 U8.7 | length 4.1
  Bottom Layer w0.254: U8.7@15.525,45.481 15.545,45.461 15.545,44.648 16.098,44.095 16.483,44.095 C121.1@16.831,43.747 16.831,42.161 R30.1@16.821,42.161
NetC122_1: C122.1 R33.1 U8.4 | length 5.1
  Bottom Layer w0.254: U8.4@15.525,49.881 15.545,49.9 15.545,50.713 15.949,51.117 16.523,51.117 16.696,51.29 16.696,51.546 17.402,52.252 C122.1@17.427,52.252 17.414,52.265 R33.1@17.414,53.864
NetC123_2: C123.2 C124.1 R136.2 U18.2 | length 6.3
  Bottom Layer w0.508: U18.2@60.81,156.955 63.11,156.955 63.331,157.176 C124.1@63.331,157.182 63.368,157.144 65.298,157.144 R136.2@65.336,157.107 65.355,157.126 65.355,158.747 C123.2@65.375,158.767
NetC124_2: C124.2 C127.1 R140.2 U18.3 | length 6.2
  Bottom Layer w0.508: U18.3@60.81,155.685 63.227,155.685 63.362,155.551 65.305,155.551 R140.2@65.336,155.52 C127.1@65.336,153.962
NetC125_1: C125.1 C134.1 R137.2 R142.2 | length 93.7
  Top Layer w0.254: v1@42.456,156.755 v1@43.351,157.65
  Inner Layer1 w0.254: v1(42.451,156.755) v1@42.456,156.755 ; v1@43.351,157.65 v1(43.356,157.65)
  Bottom Layer w0.254: R142.2@13.455,81.002 13.619,81.002 13.619,83.237 14.783,84.401 15.917,85.535 15.917,123.994 18.415,126.492 18.415,132.501 42.383,156.469 42.383,156.687 v1(42.451,156.755) ; v1(43.356,157.65) C125.1@44.613,157.65 C134.1@44.613,159.3 ; C125.1@44.648,157.66 46.267,157.66 R137.2@46.277,157.671
NetC125_2: C125.2 C133.1 R138.2 R141.2 | length 94.6
  Top Layer w0.254: v1(41.287,156.541) 41.383,156.541 41.861,156.062 v1(43.351,156.062)
  Bottom Layer w0.254: R138.2@11.944,81.019 12.144,81.019 13.042,81.918 13.042,83.307 15.459,85.724 15.459,124.298 17.907,126.746 17.907,132.65 41.287,156.03 v1(41.287,156.541) ; v1(43.351,156.062) 44.601,156.062 44.628,156.034 46.262,156.034 R141.2@46.277,156.019 ; C133.1@44.576,154.451 C125.2@44.576,156.014
  Bottom Layer w0.508: C133.1@44.54,154.415 C133.1@44.576,154.451
NetC129_1: C129.1 C130.1 L13.1 U18.1 | length 5.5
  Bottom Layer w0.508: U18.1@60.81,158.225 60.84,158.225 60.886,158.271 C130.1@60.886,160.34 C129.1@62.606,160.34 L13.1@64.231,160.34
NetC131_1: C131.1 C132.1 L14.1 U18.8 | length 5.4
  Bottom Layer w0.508: L14.1@46.559,160.267 C131.1@48.229,160.267 48.235,160.274 49.926,160.274 C132.1@49.933,160.281 49.933,158.248 U18.8@49.91,158.225
NetC136_1: C136.1 R42.1 U8.9 | length 3.5
  Bottom Layer w0.254: U8.9@14.525,45.481 14.525,44.168 C136.1@14.972,43.722 ; R42.1@14.964,42.177 14.972,42.177 C136.1@14.972,43.722 ; C136.1@14.972,43.747 C136.1@14.972,43.722
NetC137_1: C137.1 R86.1 U8.2 | length 4.8
  Bottom Layer w0.254: U8.2@14.525,49.881 14.545,49.9 14.545,50.72 15.287,51.462 15.287,51.904 15.635,52.252 C137.1@15.747,52.252 ; C137.1@15.66,52.252 15.752,52.345 R86.1@15.752,53.769 ; R86.1@15.752,53.769 R86.1@15.657,53.864 R86.1@15.752,53.769
NetC139_1: C139.1 C272.1 R152.1 R158.2 U21.2 | length 11.5
  Top Layer w0.508: R152.1@66.455,151.137 66.58,151.137 67.377,150.34 v1(67.52,150.34)
  Bottom Layer w0.508: U21.2@60.853,147.552 60.89,147.589 63.063,147.589 C139.1@63.1,147.627 R158.2@64.818,147.627 ; C272.1@64.838,149.164 64.828,149.154 64.828,147.637 R158.2@64.818,147.627 ; v1(67.52,150.34) 67.52,149.092 66.055,147.627 R158.2@64.818,147.627
NetC141_1: C141.1 C142.1 L18.1 U21.8 | length 5.4
  Bottom Layer w0.254: L18.1@44.884,149.685 C142.1@46.479,149.685
  Bottom Layer w0.508: C142.1@46.479,149.685 C141.1@48.106,149.685 48.106,149.66 48.898,148.868 49.307,148.868 49.353,148.822 U21.8@49.953,148.822
NetC143_1: C143.1 C144.1 L17.1 U21.1 | length 5.9
  Bottom Layer w0.508: U21.1@60.853,148.822 60.853,149.848 61.768,150.763 C144.1@61.768,150.788 C143.1@63.388,150.788 ; C143.1@63.388,150.813 64.411,150.813 64.812,151.214 64.812,151.239 65.033,151.46 L17.1@65.058,151.46
NetC151_1: C151.1 R163.2 R169.1 U25.3 | length 5.4
  Bottom Layer w0.254: U25.3@8.225,83.548 9.705,83.548 10.051,83.893 11.662,83.893 R169.1@11.682,83.913 11.571,83.802 11.571,83.631 11.571,82.376 R163.2@11.684,82.264
NetC154_1: C154.1 R172.2 U26.14 | length 4.8
  Bottom Layer w0.254: R172.2@10.582,53.695 10.616,53.728 C154.1@10.616,55.414 ; C154.1@10.591,55.414 10.618,55.442 10.618,56.121 11.718,57.221 U26.14@12.493,57.221
NetC159_1: C159.1 R90.2 R186.1 U14.4 | length 7.7
  Bottom Layer w0.254: R186.1@22.53,77.381 22.53,77.406 23.732,78.608 23.858,78.608 24.206,78.956 R90.2@24.206,78.981 C159.1@25.883,78.981 25.883,79.006 27.407,80.531 U14.4@28.866,80.531
NetC160_1: C160.1 R93.2 R190.1 U24.4 | length 9.7
  Bottom Layer w0.254: R93.2@22.948,106.81 R93.2@22.6,106.462 R93.2@22.6,106.462 C160.1@24.288,106.462 ; R190.1@24.257,108.204 24.257,106.49 C160.1@24.288,106.462 ; U24.4@28.765,108.785 26.975,108.785 25.281,107.091 25.281,106.61 25.132,106.462 C160.1@24.288,106.462 C160.1@24.288,106.462
NetC161_1: C161.1 R188.1 R196.2 U14.34 | length 11.6
  Top Layer w0.254: v1(41.886,79.478) 41.886,79.509 42.796,80.419 42.796,80.986 43.697,81.887 v1(44.456,81.887)
  Bottom Layer w0.254: U14.34@38.816,79.881 40.107,79.881 40.255,79.732 40.255,79.276 40.295,79.236 40.295,78.616 40.798,78.113 42.054,78.113 R196.2@42.213,78.272 42.213,79.085 41.886,79.412 v1(41.886,79.478) ; v1(44.456,81.887) 45.778,81.887 R188.1@45.92,82.029
NetC162_1: C162.1 R189.1 R197.2 U14.33 | length 9.5
  Bottom Layer w0.254: U14.33@38.816,80.531 38.905,80.441 40.355,80.441 40.744,80.052 41.432,80.052 41.439,80.058 42.246,80.058 42.962,79.343 43.497,78.808 43.497,78.581 43.965,78.113 45.277,78.113 45.548,78.384 46.892,78.384 R189.1@47.039,78.531
NetC163_1: C163.1 R191.1 R198.2 U24.34 | length 13.5
  Inner Layer1 w0.254: v1(42.096,107.485) 43.391,107.485 44.026,106.85 45.241,106.85 46.749,108.358 v1(46.749,109.086)
  Bottom Layer w0.254: U24.34@38.715,108.135 38.81,108.04 39.954,108.04 40.595,107.4 C163.1@40.595,106.374 R198.2@42.192,106.374 42.192,107.322 42.096,107.418 v1(42.096,107.485) ; v1(46.749,109.086) 46.749,110.323 R191.1@46.782,110.357
NetC164_1: C164.1 R192.1 R199.2 U24.33 | length 10.4
  Bottom Layer w0.254: U24.33@38.715,108.785 38.81,108.69 39.951,108.69 40.576,108.065 42.887,108.065 43.559,107.393 43.559,106.622 C164.1@43.807,106.374 ; C164.1@43.837,106.374 R199.2@45.4,106.374 45.4,106.349 45.748,106.001 45.795,106.001 46.997,104.799 R192.1@46.997,104.774
NetC175_1: C175.1 R200.2 U29.10 | length 4.4
  Bottom Layer w0.254: C175.1@26.656,90.716 R200.2@26.656,92.351 26.681,92.351 27.3,92.97 U29.10@29.116,92.97
NetC180_1: C180.1 R201.2 U30.10 | length 4.2
  Bottom Layer w0.254: C180.1@26.544,119.377 R201.2@26.544,120.989 28.268,120.989 28.49,121.211 U30.10@29.015,121.211
NetC183_1: C183.1 R202.2 U29.11 | length 4.2
  Bottom Layer w0.254: R202.2@26.656,94.029 R202.2@26.852,94.225 ; C183.1@26.659,95.71 26.656,95.707 26.656,94.24 26.852,94.24 U29.11@29.116,94.24
NetC184_1: C184.1 R203.2 U30.11 | length 4.1
  Bottom Layer w0.254: C184.1@26.544,124.206 R203.2@26.544,122.597 26.66,122.481 U30.11@29.015,122.481
NetC185_1: C185.1 R220.2 U29.14 | length 9.6
  Bottom Layer w0.254: C185.1@21.605,99.284 21.6,99.279 21.6,97.572 21.761,97.411 22.701,97.411 23.34,98.05 U29.14@29.116,98.05
NetC188_1: C188.1 R217.1 R223.2 U29.2 | length 11.4
  Top Layer w0.254: v1(44.279,99.95) 46.514,99.95 v1(47.009,99.455)
  Bottom Layer w0.254: U29.2@38.866,99.32 39.032,99.487 40.049,99.487 40.939,100.377 41.14,100.377 41.493,100.73 41.493,100.745 R223.2@43.084,100.745 43.084,100.72 43.527,100.276 43.932,100.276 44.259,99.95 v1(44.279,99.95) ; v1(47.009,99.455) 47.739,98.725 R217.1@48.813,98.725
NetC189_1: C189.1 R155.1 R171.2 U30.2 | length 7.2
  Bottom Layer w0.254: U30.2@38.765,127.561 39.29,127.561 40.953,129.224 41.134,129.224 41.482,129.572 C189.1@41.482,129.597 R171.2@43.082,129.597 43.167,129.512 R155.1@45.061,129.512
NetC190_1: C190.1 R214.2 U30.14 | length 9.2
  Bottom Layer w0.254: C190.1@21.6,127.629 21.6,126.038 21.757,125.881 22.827,125.881 23.236,126.291 U30.14@29.015,126.291
NetC193_1: C193.1 C195.1 R61.2 R159.2 | length 89.3
  Bottom Layer w0.254: R159.2@16.69,81.17 16.497,81.17 16.374,81.293 16.374,123.689 18.923,126.238 18.923,132.363 33.862,147.302 44.145,147.302 44.656,147.813 C193.1@44.656,147.838 ; C195.1@42.912,149.81 43.037,149.685 43.196,149.685 43.544,149.337 43.544,148.975 44.656,147.863 C193.1@44.656,147.838 ; R61.2@46.446,147.897 44.715,147.897 C193.1@44.656,147.838
NetC193_2: C193.2 C194.1 R63.2 R156.2 | length 87.7
  Bottom Layer w0.254: R156.2@18.088,81.14 17.888,81.14 17.765,81.263 17.765,81.832 16.831,82.766 16.831,123.384 19.431,125.984 19.431,132.224 33.937,146.73 44.159,146.73 44.279,146.611 44.308,146.611 44.656,146.263 C193.2@44.656,146.238 ; C194.1@44.729,144.556 44.656,144.629 C193.2@44.656,146.238 ; R63.2@46.424,146.255 44.674,146.255 C193.2@44.656,146.238
NetC197_1: C197.1 R230.2 U31.14 | length 5.1
  Bottom Layer w0.254: R230.2@15.49,6.939 15.819,6.61 15.819,4.904 C197.1@15.549,4.634 17.873,4.634 17.964,4.725 U31.14@17.964,4.777
NetC202_1: C202.1 R94.2 R244.1 U27.4 | length 8.9
  Bottom Layer w0.254: U27.4@282.475,74.255 283.801,74.255 284.753,75.207 285.49,75.207 286.79,76.507 C202.1@286.79,76.532 ; C202.1@286.79,76.555 288.56,76.555 R94.2@288.583,76.532 288.826,76.289 R244.1@290.347,76.289
NetC203_1: C203.1 R99.2 R248.1 U28.4 | length 8.8
  Bottom Layer w0.254: U28.4@282.475,45.77 283.886,45.77 284.344,46.228 285.217,46.228 286.432,47.443 286.457,47.443 286.805,47.791 C203.1@286.805,47.816 ; C203.1@286.805,47.808 R99.2@288.502,47.808 ; R99.2@288.48,47.786 R99.2@288.502,47.808 ; R248.1@290.246,47.536 288.789,47.536 R99.2@288.51,47.816 R99.2@288.502,47.808
NetC204_1: C204.1 R246.1 R255.2 U27.34 | length 12.8
  Top Layer w0.254: v1(267.7,72.956) 267.703,72.96 268.331,72.96 269.144,73.773 269.144,75.189 269.542,75.587 v1(269.542,75.653)
  Bottom Layer w0.254: R246.1@265.328,70.695 265.353,70.695 266.51,71.852 266.596,71.852 v1(267.7,72.956) ; R255.2@269.181,76.682 269.529,76.334 269.529,75.666 v1(269.542,75.653) ; R255.2@269.247,76.677 269.409,76.839 C204.1@270.633,76.839 ; C204.1@270.72,76.682 270.72,75.772 271.492,75 272.43,75 U27.34@272.525,74.905
NetC205_1: C205.1 R247.1 R256.2 U27.33 | length 9.5
  Bottom Layer w0.254: R247.1@266.119,75.055 R256.2@266.119,76.682 266.281,76.843 267.49,76.843 267.994,76.339 267.994,75.813 268.156,75.651 268.793,75.014 270.832,75.014 271.27,74.576 271.27,74.572 271.492,74.35 272.43,74.35 U27.33@272.525,74.255
NetC206_1: C206.1 R249.1 R257.2 U28.34 | length 11.8
  Top Layer w0.254: v1@268.025,44.137 269.913,46.025 v1(269.913,47.166)
  Bottom Layer w0.254: R249.1@266.711,43.261 266.736,43.261 267.386,43.911 v1(268.036,43.911) ; v1(269.913,47.166) 269.318,47.166 269.088,47.396 R257.2@269.088,48.207 C206.1@270.702,48.207 271.05,47.859 271.05,46.957 271.492,46.515 272.43,46.515 U28.34@272.525,46.42
NetC207_1: C207.1 R250.1 R258.2 U28.33 | length 10
  Bottom Layer w0.254: R250.1@265.241,46.57 265.241,47.583 265.88,48.222 R258.2@265.88,48.247 267.465,48.247 C207.1@267.505,48.207 267.642,48.07 267.642,47.474 268.531,46.586 270.597,46.586 271.393,45.79 272.505,45.79 U28.33@272.525,45.77
NetC217_1: C217.1 R259.2 U34.10 | length 4
  Bottom Layer w0.254: U34.10@282.225,61.975 282.75,61.975 282.94,62.165 284.49,62.165 284.485,62.17 C217.1@284.485,63.85
NetC222_1: C222.1 R260.2 U35.10 | length 4
  Bottom Layer w0.254: U35.10@282.225,33.328 284.273,33.328 R260.2@284.525,33.58 C222.1@284.525,35.211
NetC225_1: C225.1 R261.2 U34.11 | length 4
  Bottom Layer w0.254: U34.11@282.225,60.705 284.34,60.705 284.49,60.555 284.49,58.923 C225.1@284.485,58.917
NetC226_1: C226.1 R262.2 U35.11 | length 4.4
  Bottom Layer w0.254: U35.11@282.75,32.058 U35.11@282.225,32.058 284.447,32.058 R262.2@284.525,31.979 ; C226.1@284.525,30.354 284.528,30.354 284.528,31.876 R262.2@284.529,31.878
NetC227_1: C227.1 R279.2 U34.14 | length 8.7
  Bottom Layer w0.254: U34.14@282.225,56.895 287.534,56.895 288.73,55.699 288.73,55.674 289.085,55.674 R279.2@290.41,55.674
NetC230_1: C230.1 R276.1 R282.2 U34.2 | length 21.6
  Top Layer w0.254: v1(256.531,60.534) 262.388,54.677 v1(266.94,54.677)
  Bottom Layer w0.254: v1(256.531,60.534) 257.063,61.066 R276.1@257.063,61.975 R276.1@256.789,61.701 ; v1(266.94,54.677) 266.954,54.663 267.311,54.663 267.857,54.116 267.882,54.116 268.23,53.768 R282.2@268.23,53.743 C230.1@269.816,53.743 269.816,53.768 270.164,54.116 270.441,54.116 271.95,55.625 U34.2@272.475,55.625
NetC231_1: C231.1 R280.2 U35.14 | length 9.1
  Bottom Layer w0.254: U35.14@282.225,28.248 283.373,28.248 283.733,27.888 287.872,27.888 288.12,27.641 288.122,27.641 288.955,26.808 C231.1@288.955,26.783 290.64,26.783 R280.2@290.652,26.771
NetC232_1: C232.1 R104.2 R287.1 U32.4 | length 7.4
  Bottom Layer w0.254: R287.1@22.712,49.7 22.712,49.725 23.896,50.909 24.112,50.909 24.46,51.257 R104.2@24.46,51.282 C232.1@26.086,51.282 26.086,51.307 27.243,52.465 U32.4@28.905,52.465
NetC235_1: C235.1 R278.1 R284.2 U35.2 | length 26.9
  Top Layer w0.254: v1(256.716,37.66) 259.28,35.097 262.34,35.097 266.084,31.352 267.461,29.976 267.461,26.417 v1(266.596,25.552)
  Bottom Layer w0.254: v1(256.716,37.66) 256.784,37.728 256.784,38.219 256.94,38.375 256.94,38.4 257.288,38.748 R278.1@257.313,38.748 ; v1(266.596,25.552) 267.027,25.121 R284.2@268.113,25.121 ; R284.2@268.113,25.096 C235.1@269.738,25.096 270.075,25.433 270.406,25.433 271.95,26.978 U35.2@272.475,26.978
NetC236_1: C236.1 R130.2 R292.1 U33.4 | length 7.5
  Bottom Layer w0.254: R292.1@22.784,20.155 22.784,20.18 23.998,21.395 24.163,21.395 24.511,21.743 R130.2@24.511,21.768 C236.1@26.162,21.768 26.162,21.793 27.7,23.33 28.81,23.33 U33.4@28.905,23.425
NetC240_1: C240.1 R289.1 R298.2 U32.34 | length 14.9
  Top Layer w0.254: v1(42.021,50.981) 43.304,52.263 v1(43.304,54.379)
  Bottom Layer w0.254: U32.34@38.95,51.72 U32.34@38.855,51.815 39.984,51.815 40.623,51.177 40.623,50 40.771,49.852 42.131,49.852 42.26,49.981 42.021,50.219 v1(42.021,50.981) ; v1(43.304,54.379) 45.412,54.379 45.561,54.23 45.561,53.115 46.525,52.151 R289.1@46.525,52.126
NetC241_1: C241.1 R290.1 R299.2 U32.33 | length 10.4
  Bottom Layer w0.254: U32.33@38.855,52.465 38.95,52.37 40.076,52.37 40.885,51.561 42.667,51.561 43.522,50.705 43.522,50.354 44,49.877 44,49.852 45.348,49.852 45.477,49.981 R299.2@45.561,49.897 45.561,49.872 46.763,48.67 46.786,48.67 47.134,48.322 R290.1@47.134,48.297
NetC242_1: C242.1 R293.1 R301.2 U33.34 | length 11
  Top Layer w0.254: v1(42.358,21.804) 42.358,23.391 v1(43.747,24.78)
  Bottom Layer w0.254: U33.34@38.855,22.775 38.906,22.724 39.956,22.724 40.363,22.318 40.363,21.071 C242.1@40.711,20.723 R301.2@42.303,20.723 42.358,20.779 v1(42.358,21.804) ; v1(43.747,24.78) R293.1@45.082,24.78
NetC243_1: C243.1 R294.1 R302.2 U33.33 | length 9.8
  Bottom Layer w0.254: U33.33@38.855,23.425 38.908,23.372 39.954,23.372 40.815,22.511 42.544,22.511 43.637,21.419 43.637,21.033 C243.1@43.947,20.723 R302.2@45.55,20.723 45.55,20.748 46.469,20.748 47.052,21.332 R294.1@47.052,21.357
NetC254_1: C254.1 R303.2 U37.10 | length 4.1
  Bottom Layer w0.254: C254.1@26.745,34.059 R303.2@26.745,35.679 26.93,35.865 U37.10@29.155,35.865
NetC259_1: C259.1 R304.2 U38.10 | length 4.3
  Bottom Layer w0.254: C259.1@26.697,62.756 26.695,62.758 26.695,64.405 R304.2@26.697,64.406 26.722,64.406 27.22,64.905 U38.10@29.155,64.905
NetC262_1: C262.1 R305.2 U37.11 | length 4.1
  Bottom Layer w0.254: C262.1@26.745,38.914 R305.2@26.745,37.297 26.907,37.135 U37.11@29.155,37.135
NetC264_1: C264.1 R306.2 U38.11 | length 4.3
  Bottom Layer w0.254: R306.2@26.697,66.006 26.697,66.173 R306.2@26.695,66.175 ; C264.1@26.697,67.704 26.695,67.702 R306.2@26.695,66.175 ; U38.11@29.116,66.007 29.155,66.046 29.155,66.175 26.892,66.175 R306.2@26.695,66.175
NetC265_1: C265.1 R323.2 U37.14 | length 9.2
  Bottom Layer w0.254: R323.2@21.114,42.147 C265.1@22.488,42.147 ; C265.1@22.737,42.147 C265.1@22.488,42.147 ; U37.14@29.155,40.745 28.982,40.918 28.365,40.918 28.308,40.975 23.261,40.975 22.712,41.524 22.712,41.799 22.426,42.085 C265.1@22.488,42.147
NetC269_1: C269.1 R320.1 R325.2 U37.2 | length 15
  Top Layer w0.254: v1(44.269,43.747) 45.209,43.747 47.93,41.026 47.93,39.741 v1(48.867,38.803)
  Bottom Layer w0.254: U37.2@38.905,42.015 39.43,42.015 40.939,43.524 41.23,43.524 41.578,43.872 C269.1@41.578,43.897 R325.2@43.165,43.897 43.315,43.747 v1(44.269,43.747) ; v1(48.867,38.803) R320.1@50.216,38.803
NetC270_1: C270.1 R324.2 U38.14 | length 8.9
  Bottom Layer w0.254: C270.1@22.751,72.788 22.9,72.639 22.9,71.234 R324.2@22.759,71.094 22.759,71.069 22.822,71.007 23.844,69.985 29.155,69.985 29.155,69.856 U38.14@29.116,69.817
NetC277_1: C277.1 R134.2 R330.1 U39.4 | length 8.7
  Bottom Layer w0.254: U39.4@282.475,130.18 283.789,130.18 284.306,130.696 284.971,130.696 286.759,132.484 286.759,132.506 288.441,132.506 R134.2@288.444,132.509 288.513,132.441 R330.1@288.513,130.739
NetC278_1: C278.1 R331.1 R335.2 U39.34 | length 11.7
  Top Layer w0.254: v1(264.672,132.2) 268.45,132.2 268.877,131.773 v1(268.916,131.773)
  Bottom Layer w0.254: R331.1@264.405,131.133 264.672,131.4 v1(264.672,132.2) ; v1(268.916,131.773) 268.916,132.753 R335.2@268.998,132.834 270.619,132.834 C278.1@270.622,132.831 270.97,132.483 270.97,131.447 271.492,130.925 272.43,130.925 U39.34@272.525,130.83
NetC279_1: C279.1 R332.1 R336.2 U39.33 | length 9.9
  Bottom Layer w0.254: R336.2@265.755,132.831 R336.2@265.78,132.806 ; R332.1@266.047,131.133 265.78,131.4 R336.2@265.78,132.806 ; U39.33@272.525,130.18 272.43,130.275 271.347,130.275 270.745,130.877 268.855,130.877 268.226,131.505 268.226,131.949 267.37,132.806 R336.2@265.78,132.806
NetC282_1: C282.1 R133.2 R345.1 U36.4 | length 8.8
  Bottom Layer w0.254: U36.4@282.426,102.288 282.521,102.383 283.866,102.383 284.551,103.068 285.443,103.068 286.706,104.332 C282.1@286.706,104.357 286.708,104.355 R133.2@288.362,104.355 ; R133.2@288.187,104.181 R133.2@288.362,104.355 ; R345.1@290.068,104.203 289.914,104.357 R133.2@288.363,104.357 R133.2@288.362,104.355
